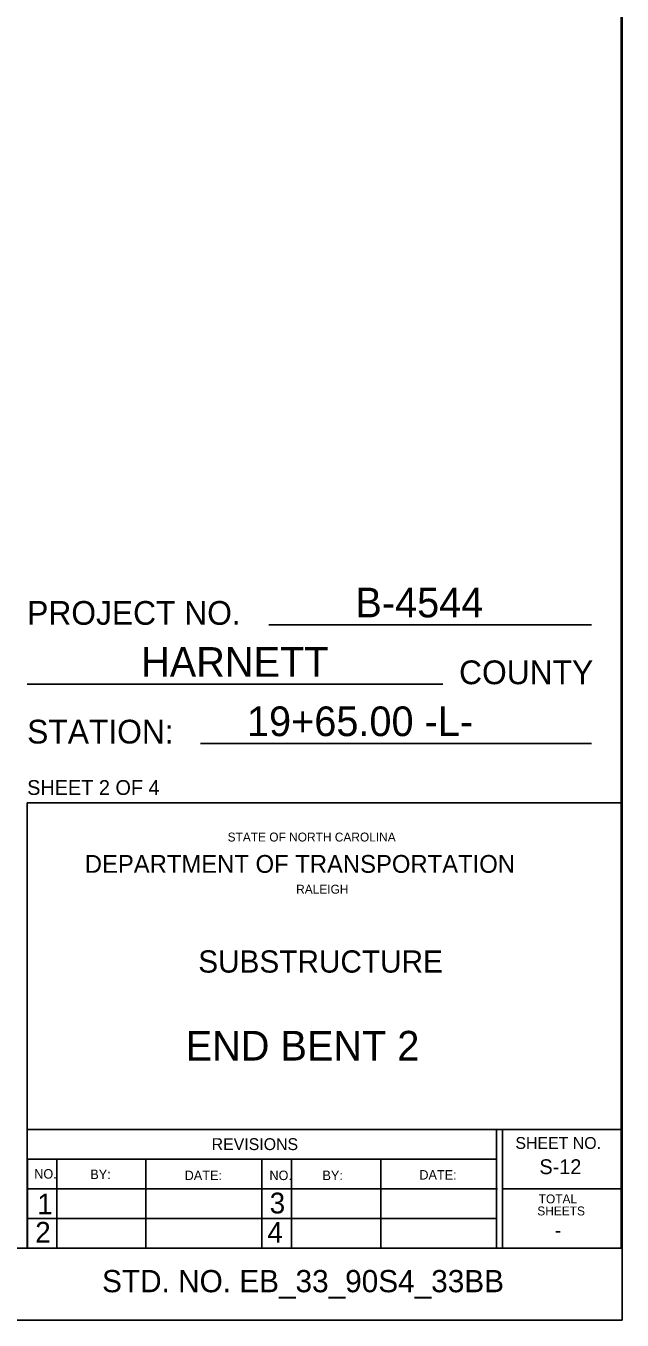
# Model space of a CAD drawing. Extents: x -41 to 251, y -169 to 237.
# Drawn here: x 149.93 to 161.43, y -50.55 to -25.59 of the extents above; entities that cross this region are included whole.
import ezdxf

# ---------------------------------------------------------------- set-up
doc = ezdxf.new("R2010")
doc.units = 0
for name, color, linetype in [('Plan Sheet CELL', 7, 'Continuous'), ('Plot Shape CELL', 7, 'Continuous'), ('Subtitle Text', 7, 'Continuous'), ('Text', 7, 'Continuous'), ('Title Text', 7, 'Continuous')]:
    doc.layers.add(name, color=color, linetype=linetype)

msp = doc.modelspace()

# ---------------------------------------------------------------- linework, layer by layer
at = {"layer": 'Plan Sheet CELL'}
for p, q in [((161.409, -1.076), (161.409, -49.166)), ((160.837, -37.142), (154.615, -37.142)), ((157.974, -38.288), (149.959, -38.288)), ((160.837, -39.432), (153.303, -39.432)), ((161.409, -40.577), (149.959, -40.577)), ((149.959, -40.577), (149.959, -49.166)), ((149.959, -46.875), (161.409, -46.875)), ((159.005, -46.875), (159.005, -49.166)), ((159.12, -46.875), (159.12, -49.166)), ((149.959, -47.447), (159.01, -47.447)), ((149.966, -47.447), (149.966, -49.166)), ((150.531, -47.447), (150.531, -49.166)), ((152.249, -47.457), (152.249, -49.174)), ((154.484, -47.447), (154.484, -49.18)), ((155.057, -47.447), (155.057, -49.167)), ((156.775, -47.447), (156.775, -49.167)), ((149.959, -48.02), (159.028, -48.02)), ((159.12, -48.02), (161.389, -48.02)), ((149.959, -48.592), (159.01, -48.592)), ((88.128, -49.166), (161.409, -49.166)), ((161.429, -50.554), (161.429, -50.554))]:
    msp.add_line(p, q, dxfattribs=at)
at = {"layer": 'Plot Shape CELL'}
msp.add_lwpolyline([(85.715, -0.174), (161.429, -0.174), (161.429, -50.554), (85.715, -50.554)], close=True, dxfattribs=at)

# ---------------------------------------------------------------- texts
at = {"layer": 'Plan Sheet CELL'}
for s, height, p in [('PROJECT NO.', 0.458, (149.959, -37.142)), ('COUNTY', 0.458, (158.286, -38.288)), ('STATION:', 0.458, (149.959, -39.432)), ('SHEET 2 OF 4', 0.28625, (149.959, -40.424)), ('STATE OF NORTH CAROLINA', 0.17174, (153.823, -41.322)), ('DEPARTMENT OF TRANSPORTATION', 0.34349, (151.07, -41.926)), ('RALEIGH', 0.1717, (155.145, -42.328)), ('REVISIONS', 0.229, (153.515, -47.274)), ('SHEET NO.', 0.229, (159.372, -47.252)), ('NO.', 0.1825, (150.095, -47.824)), ('BY:', 0.1825, (151.176, -47.833)), ('DATE:', 0.1825, (152.995, -47.853)), ('NO.', 0.1825, (154.63, -47.853)), ('BY:', 0.1825, (155.652, -47.854)), ('DATE:', 0.1825, (157.52, -47.843)), ('1', 0.401, (150.155, -48.515)), ('3', 0.401, (154.634, -48.496)), ('TOTAL', 0.1717, (159.821, -48.302)), ('SHEETS', 0.1717, (159.794, -48.534)), ('2', 0.401, (150.114, -49.06)), ('4', 0.401, (154.591, -49.06))]:
    msp.add_text(s, height=height, dxfattribs=at).set_placement(p)
at = {"layer": 'Subtitle Text'}
for s, p in [('SUBSTRUCTURE', (153.257, -43.851)), ('STD. NO. EB_33_90S4_33BB', (151.403, -50.016))]:
    msp.add_text(s, height=0.429, dxfattribs=at).set_placement(p)
at = {"layer": 'Text'}
for s, p in [('S-12', (159.835, -47.738)), ('-', (160.128, -48.96))]:
    msp.add_text(s, height=0.286, dxfattribs=at).set_placement(p)
at = {"layer": 'Title Text'}
for s, p in [('B-4544', (156.287, -36.999)), ('HARNETT', (152.156, -38.145)), ('19+65.00 -L-', (154.197, -39.289)), ('END BENT 2', (153.015, -45.547))]:
    msp.add_text(s, height=0.572, dxfattribs=at).set_placement(p)

doc.saveas('drawing.dxf')
